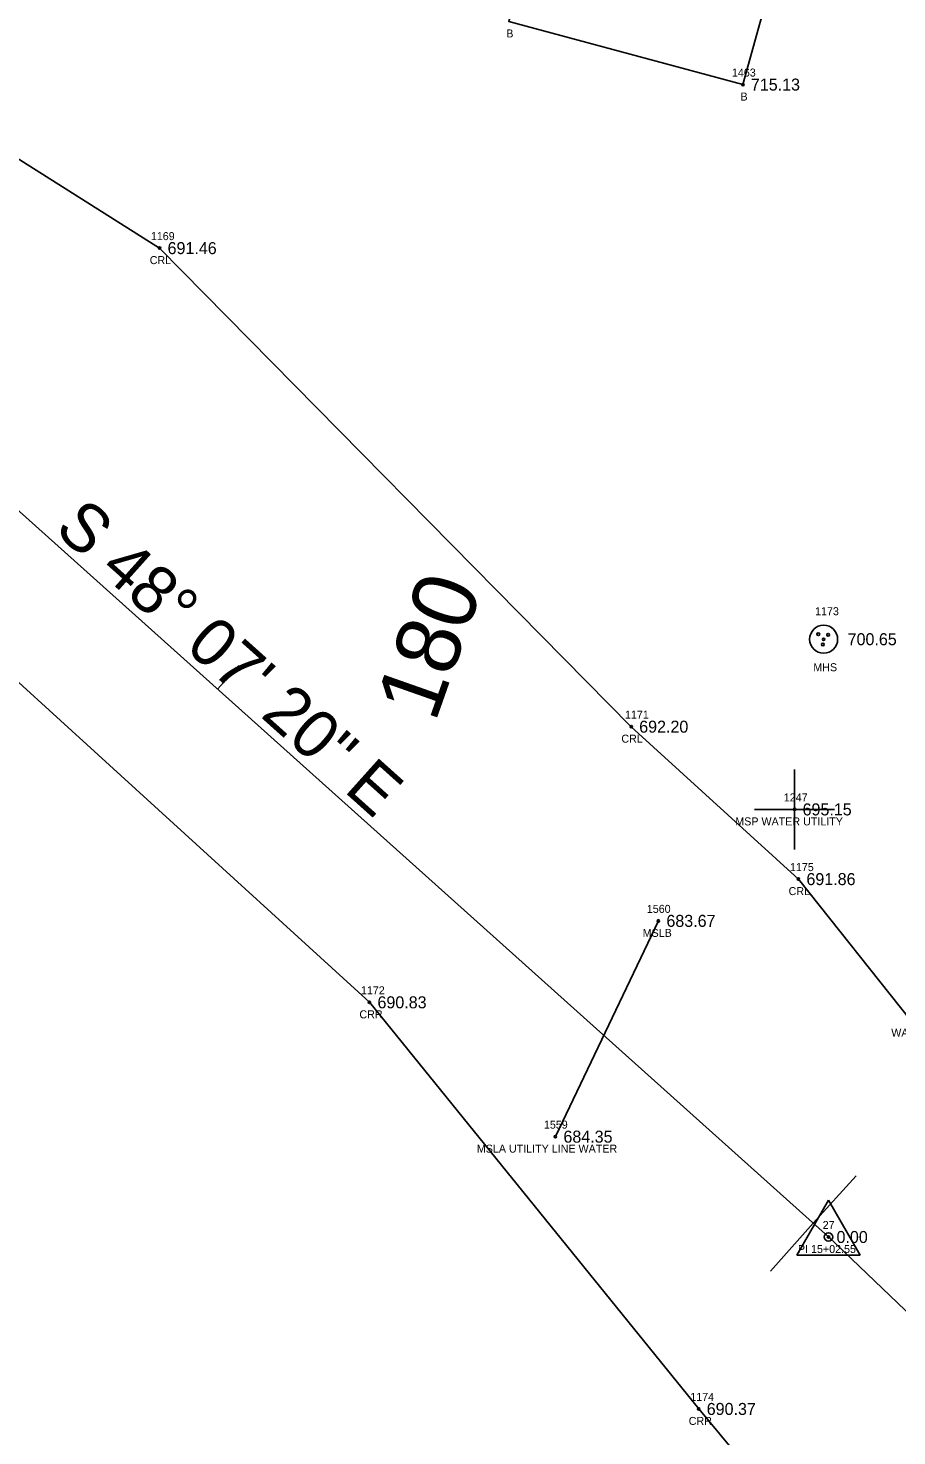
# Model space of a CAD drawing. Extents: x 1736563 to 1738032, y 1150548 to 1154248.
# Drawn here: x 1737284.7 to 1737393.3, y 1152683.1 to 1152859 of the extents above; entities that cross this region are included whole.
import ezdxf

# ---------------------------------------------------------------- set-up
doc = ezdxf.new("R2010")
doc.units = 0
for name, color, linetype in [('RD_EX_Bldg', 7, 'Continuous'), ('RD_EX_Bldg_txCode', 7, 'Continuous'), ('RD_EX_DR_Inlet', 7, 'Continuous'), ('RD_EX_H2O', 7, 'Continuous'), ('RD_EX_H2O_txCode', 7, 'Continuous'), ('RD_EX_Misc', 7, 'Continuous'), ('RD_EX_Misc_txCode', 7, 'Continuous'), ('RD_EX_TX_Bldg_ELEV', 7, 'Continuous'), ('RD_EX_TX_H2O_ELEV', 7, 'Continuous'), ('RD_EX_TX_Misc_ELEV', 7, 'Continuous'), ('RD_EX_TX_UT_ELEV', 7, 'Continuous'), ('RD_EX_UT_txCode', 7, 'Continuous'), ('RD_HC_Cl', 7, 'Continuous'), ('RD_HC_Data', 7, 'Continuous'), ('RD_HC_Data_Tic', 7, 'Continuous'), ('RD_HC_Survey_ELEV', 7, 'Continuous'), ('RD_HC_TX_Sta50', 7, 'Continuous'), ('RD_HC_txCode', 7, 'Continuous'), ('RD_SMD_Locator', 7, 'Continuous')]:
    doc.layers.add(name, color=color, linetype=linetype)

msp = doc.modelspace()

# ---------------------------------------------------------------- linework, layer by layer
at = {"layer": 'RD_EX_Bldg'}
msp.add_lwpolyline([(1737351.26, 1152883.28), (1737380.52, 1152875.38), (1737374.05, 1152851.97), (1737344.79, 1152859.86), (1737351.26, 1152883.28)], dxfattribs=at)
at = {"layer": 'RD_EX_DR_Inlet'}
for centre, radius in [((1737384.14, 1152782.65), 1.75), ((1737383.47, 1152783.28), 0.175), ((1737384.05, 1152781.98), 0.175), ((1737384.7, 1152783.21), 0.175)]:
    msp.add_circle(centre, radius, dxfattribs=at)
at = {"layer": 'RD_EX_H2O'}
for points in [[(1736960.44, 1152971.53), (1737057.49, 1152938.22), (1737130.09, 1152902.43), (1737229.47, 1152876.86), (1737301.15, 1152831.53), (1737360.09, 1152771.72), (1737380.99, 1152752.67), (1737395.02, 1152734.98)], [(1736941.84, 1152927.33), (1737042.79, 1152891.61), (1737121.65, 1152865.9), (1737201.8, 1152833.83), (1737271.75, 1152787.96), (1737327.38, 1152737.27), (1737368.53, 1152686.45), (1737382.66, 1152669.43)]]:
    msp.add_lwpolyline(points, dxfattribs=at)
at = {"layer": 'RD_EX_Misc'}
for p, q in [((1737380.51, 1152756.38), (1737380.51, 1152766.38)), ((1737375.51, 1152761.38), (1737385.51, 1152761.38)), ((1737350.62, 1152720.48), (1737363.49, 1152747.45))]:
    msp.add_line(p, q, dxfattribs=at)
at = {"layer": 'RD_HC_Cl'}
for p, q in [((1737233.34, 1152843.69), (1737384.75, 1152707.94)), ((1737384.75, 1152707.94), (1737485.65, 1152611.3))]:
    msp.add_line(p, q, dxfattribs=at)
at = {"layer": 'RD_HC_Data'}
for p, q in [((1737380.78, 1152705.65), (1737384.75, 1152712.53)), ((1737384.75, 1152712.53), (1737388.72, 1152705.65)), ((1737380.78, 1152705.65), (1737388.72, 1152705.65))]:
    msp.add_line(p, q, dxfattribs=at)
msp.add_circle((1737384.75, 1152707.94), 0.529, dxfattribs=at)
at = {"layer": 'RD_HC_Data_Tic'}
for p, q in [((1737308.39, 1152776.4), (1737311.06, 1152779.38)), ((1737382.85, 1152709.65), (1737388.19, 1152715.6)), ((1737382.85, 1152709.65), (1737377.51, 1152703.69))]:
    msp.add_line(p, q, dxfattribs=at)
at = {"layer": 'RD_SMD_Locator'}
for centre in [(1737374.05, 1152851.97), (1737301.15, 1152831.53), (1737384.14, 1152782.65), (1737360.09, 1152771.72), (1737380.51, 1152761.38), (1737380.99, 1152752.67), (1737363.49, 1152747.45), (1737327.38, 1152737.27), (1737350.62, 1152720.48), (1737384.75, 1152707.94), (1737368.53, 1152686.45)]:
    msp.add_circle(centre, 0.15, dxfattribs=at)

# ---------------------------------------------------------------- texts
at = {"layer": 'RD_EX_Bldg_txCode'}
for s, p in [('B', (1737344.48, 1152857.86)), ('1463', (1737372.68, 1152852.97)), ('B', (1737373.75, 1152849.97))]:
    msp.add_text(s, height=1, dxfattribs=at).set_placement(p)
at = {"layer": 'RD_EX_H2O_txCode'}
for s, p in [('1169', (1737300.06, 1152832.53)), ('CRL', (1737299.92, 1152829.53)), ('1171', (1737359.31, 1152772.72)), ('CRL', (1737358.86, 1152769.72)), ('1175', (1737379.93, 1152753.67)), ('CRL', (1737379.76, 1152750.67)), ('1172', (1737326.31, 1152738.27)), ('CRR', (1737326.12, 1152735.27)), ('1174', (1737367.47, 1152687.45)), ('CRR', (1737367.28, 1152684.45))]:
    msp.add_text(s, height=1, dxfattribs=at).set_placement(p)
at = {"layer": 'RD_EX_Misc_txCode'}
for s, p in [('1247', (1737379.16, 1152762.38)), ('MSP WATER UTILITY', (1737373.1, 1152759.38)), ('1560', (1737362.04, 1152748.45)), ('MSLB', (1737361.52, 1152745.45)), ('WA 12C', (1737392.59, 1152732.98)), ('1559', (1737349.18, 1152721.48)), ('MSLA UTILITY LINE WATER', (1737340.8, 1152718.48))]:
    msp.add_text(s, height=1, dxfattribs=at).set_placement(p)
at = {"layer": 'RD_EX_TX_Bldg_ELEV'}
msp.add_text('715.13', height=1.5, dxfattribs=at).set_placement((1737375.05, 1152851.22))
at = {"layer": 'RD_EX_TX_H2O_ELEV'}
for s, p in [('691.46', (1737302.15, 1152830.78)), ('692.20', (1737361.09, 1152770.97)), ('691.86', (1737381.99, 1152751.92)), ('690.83', (1737328.38, 1152736.52)), ('690.37', (1737369.53, 1152685.7))]:
    msp.add_text(s, height=1.5, dxfattribs=at).set_placement(p)
at = {"layer": 'RD_EX_TX_Misc_ELEV'}
for s, p in [('695.15', (1737381.51, 1152760.63)), ('683.67', (1737364.49, 1152746.7)), ('684.35', (1737351.62, 1152719.73))]:
    msp.add_text(s, height=1.5, dxfattribs=at).set_placement(p)
at = {"layer": 'RD_EX_TX_UT_ELEV'}
msp.add_text('700.65', height=1.5, dxfattribs=at).set_placement((1737387.14, 1152781.9))
at = {"layer": 'RD_EX_UT_txCode'}
for s, p in [('1173', (1737383.07, 1152785.65)), ('MHS', (1737382.85, 1152778.65))]:
    msp.add_text(s, height=1, dxfattribs=at).set_placement(p)
at = {"layer": 'RD_HC_Data'}
msp.add_text('S 48%%d 07\' 20" E', height=6, rotation=318.1221, dxfattribs=at).set_placement((1737287.85, 1152796.16))
at = {"layer": 'RD_HC_Survey_ELEV'}
msp.add_text('0.00', height=1.5, dxfattribs=at).set_placement((1737385.75, 1152707.19))
at = {"layer": 'RD_HC_TX_Sta50'}
msp.add_text('180', height=8, rotation=70.5857, dxfattribs=at).set_placement((1737335.57, 1152772.11))
at = {"layer": 'RD_HC_txCode'}
for s, p in [('27', (1737384.02, 1152708.94)), ('PI 15+02.55', (1737380.93, 1152705.94))]:
    msp.add_text(s, height=1, dxfattribs=at).set_placement(p)

doc.saveas('drawing.dxf')
